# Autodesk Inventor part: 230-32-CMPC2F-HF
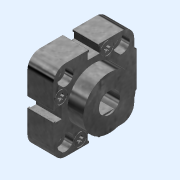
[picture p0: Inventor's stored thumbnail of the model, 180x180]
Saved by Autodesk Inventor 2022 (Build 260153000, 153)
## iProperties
Category: PARTsolutions
Company: METALWORK
Part Number: 230-32-CMPC2F-HF
Material: Generico
Catalog Web Link: www.cadenas.de
Description: CMPC2F-HF-
Vendor: METALWORK
Document SubType Name: Modeling
Designer: partserver
Manufacturer: METALWORK
Mass: 30.9361 g
Surface Area: 107.039 cm^2
Volume: 30.9361 cm^3
Density: 1 g/cm^3
Appearance: Acciaio galvanizzato
PSOL_IDENT_0: {$CADENAS_DATA\23d-libs\metalwork\actuators\comp_cyl_ser_cmpc_2_flat\parts\cmpc_2_flat_head_front.pr
PSOL_IDENT_1: j},186 {VTYP=3D},{NB=230-32-CMPC2F-HF},{LINA=230-32-CMPC2F-HF},{NN=CMPC2F-HF},{DATE=18.06.2021 08:06
PSOL_IDENT_2: :07},{GEOMDATE=01.12.2009 08:31:00},{VERSION=},{LINEID=50},{WBVAR=TYPE,VE},{WBNUMERIC=TYPE}  {NB=230
PSOL_IDENT_3: -32-CMPC2F-HF},{LINA=230-32-CMPC2F-HF},{KT=DUMMY},{IDNR=},{DI=32},{TYPE=23},{VE=0},{A=46.300},{B=32.
PSOL_IDENT_4: 25},{B2=0.000},{C=12.000},{C1=9.000},{D=47.800},{D1=9.000},{D2=7.600},{D3=7.000},{H=7.500},{H1=6.950
PSOL_IDENT_5: },{H2=5.400},{H3=14.750},{H4=2.800},{K=30.000},{L=4.500},{L1=3.700},{L2=1.200},{L3=10.000},{LD=1.700
PSOL_IDENT_6: },{O=6.000},{Q=9.728},{X=18.700},{Y=7.700},{R1=7.150},{R2=3.400},{R3=0.300},{R4=0.500},{CH=10.000}
NB: 230-32-CMPC2F-HF
NN: CMPC2F-HF
NBSYN: $TYPE.$VE.-$DI.-CMPC2F-HF
LINA: 230-32-CMPC2F-HF
CATALOG: Metalwork
DI: 32
TYPE: Centre distance to UNITOP, male rod
VE: Double-acting
A: 46.3
B: 32.25
B2: 0
C: 12
C1: 9
D: 47.8
D2: 7.6
D3: 7
H: 7.5
H1: 6.95
H2: 5.4
H3: 14.75
H4: 2.8
K: 30
L1: 3.7
L2: 1.2
L3: 10
LD: 1.7
O: 6
Q: 9.728
X: 18.7
Y: 7.7
R1: 7.15
R2: 3.4
R3: 0.3
R4: 0.5
CH: 10
SUPPLIER: METALWORK
ARTICLENO: 230-32-CMPC2F-HF
BOMINFO: 230-32-CMPC2F-HF
CREATOR: CADENAS GmbH
Title: 230-32-CMPC2F-HF
Author: Cadenas PARTsolutions
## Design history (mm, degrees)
sketch "Sketch_1"
  geometry: L1 (-23.15, 16)-(-23.15, 3.1); L2 (-22.75, 2.7)-(-22.15, 2.7); L3 (-21.95, 2.9)-(-21.95, 3.275); L4 (-21.75, 3.475)-(-18.45, 3.475); L5 (-18.25, 3.275)-(-18.25, -3.275); L6 (-18.45, -3.475)-(-21.75, -3.475); L7 (-21.95, -3.275)-(-21.95, -2.9); L8 (-22.15, -2.7)-(-22.75, -2.7); L9 (-23.15, -3.1)-(-23.15, -16); L10 (-16, -23.15)-(-3.1, -23.15); L11 (-2.7, -22.75)-(-2.7, -22.15); L12 (-2.9, -21.95)-(-3.275, -21.95); L13 (-3.475, -21.75)-(-3.475, -18.45); L14 (-3.275, -18.25)-(3.275, -18.25); L15 (3.475, -18.45)-(3.475, -21.75); L16 (3.275, -21.95)-(2.9, -21.95); L17 (2.7, -22.15)-(2.7, -22.75); L18 (3.1, -23.15)-(16, -23.15); L19 (23.15, -16)-(23.15, -10.402); L20 (23.15, -10.402)-(24.65, -10); L21 (24.65, -10)-(24.65, 10); L22 (24.65, 10)-(23.15, 10.402); L23 (23.15, 10.402)-(23.15, 16); L24 (16, 23.15)-(3.1, 23.15); L25 (2.7, 22.75)-(2.7, 22.15); L26 (2.9, 21.95)-(3.275, 21.95); L27 (3.475, 21.75)-(3.475, 18.45); L28 (3.275, 18.25)-(-3.275, 18.25); L29 (-3.475, 18.45)-(-3.475, 21.75); L30 (-3.275, 21.95)-(-2.9, 21.95); L31 (-2.7, 22.15)-(-2.7, 22.75); L32 (-3.1, 23.15)-(-16, 23.15); A1 r 7.15 centre (-16, 16) between (-16, 23.15) and (-23.15, 16); A2 r 0.4 centre (-22.75, 3.1) between (-23.15, 3.1) and (-22.75, 2.7); A3 r 0.2 centre (-22.15, 2.9) between (-22.15, 2.7) and (-21.95, 2.9); A4 r 0.2 centre (-21.75, 3.275) between (-21.75, 3.475) and (-21.95, 3.275); A5 r 0.2 centre (-18.45, 3.275) between (-18.25, 3.275) and (-18.45, 3.475); A6 r 0.2 centre (-18.45, -3.275) between (-18.45, -3.475) and (-18.25, -3.275); A7 r 0.2 centre (-21.75, -3.275) between (-21.95, -3.275) and (-21.75, -3.475); A8 r 0.2 centre (-22.15, -2.9) between (-21.95, -2.9) and (-22.15, -2.7); A9 r 0.4 centre (-22.75, -3.1) between (-22.75, -2.7) and (-23.15, -3.1); A10 r 7.15 centre (-16, -16) between (-23.15, -16) and (-16, -23.15); A11 r 0.4 centre (-3.1, -22.75) between (-3.1, -23.15) and (-2.7, -22.75); A12 r 0.2 centre (-2.9, -22.15) between (-2.7, -22.15) and (-2.9, -21.95); A13 r 0.2 centre (-3.275, -21.75) between (-3.475, -21.75) and (-3.275, -21.95); A14 r 0.2 centre (-3.275, -18.45) between (-3.275, -18.25) and (-3.475, -18.45); A15 r 0.2 centre (3.275, -18.45) between (3.475, -18.45) and (3.275, -18.25); A16 r 0.2 centre (3.275, -21.75) between (3.275, -21.95) and (3.475, -21.75); A17 r 0.2 centre (2.9, -22.15) between (2.9, -21.95) and (2.7, -22.15); A18 r 0.4 centre (3.1, -22.75) between (2.7, -22.75) and (3.1, -23.15); A19 r 7.15 centre (16, -16) between (16, -23.15) and (23.15, -16); A20 r 7.15 centre (16, 16) between (23.15, 16) and (16, 23.15); A21 r 0.4 centre (3.1, 22.75) between (3.1, 23.15) and (2.7, 22.75); A22 r 0.2 centre (2.9, 22.15) between (2.7, 22.15) and (2.9, 21.95); A23 r 0.2 centre (3.275, 21.75) between (3.475, 21.75) and (3.275, 21.95); A24 r 0.2 centre (3.275, 18.45) between (3.275, 18.25) and (3.475, 18.45); A25 r 0.2 centre (-3.275, 18.45) between (-3.475, 18.45) and (-3.275, 18.25); A26 r 0.2 centre (-3.275, 21.75) between (-3.275, 21.95) and (-3.475, 21.75); A27 r 0.2 centre (-2.9, 22.15) between (-2.9, 21.95) and (-2.7, 22.15); A28 r 0.4 centre (-3.1, 22.75) between (-2.7, 22.75) and (-3.1, 23.15)
  constraints: 64 end point, 56 point on circle, 28 centre point
extrude "Extrusion1" join sketch "Sketch_1" distance "d0" = 14.75; taper "d1" = 0 deg
sketch "Sketch2"
  geometry: 1 further point
hole "Hole1" sketch "Sketch2" at (7.5, 10) diameter "d2" = 8.566; stored, may be unused: countersink angle "d6" = 90 deg, drill point angle "d8" = 120 deg; dims "d3" = 9.728, "d4" = 4, "d5" = 2, "d7" = 14.592
sketch "Sketch_7"
  geometry: L1 (14.75, -16.125)-(0, -16.125); L2 (0, -16.125)-(0, -11.625); L3 (0, -11.625)-(4.5, -11.625); L4 (4.5, -11.625)-(4.5, -13.666); L5 (4.5, -13.666)-(14.75, -13.666); L6 (14.75, -13.666)-(14.75, -16.125); L7 (14.75, -16.125)-(0, -16.125)
  constraints: 14 end point
revolve "Revolution1" sketch "Sketch_7" stored, may be unused: angle "d9" = 360 deg
thread "Thread1" dims "d10" = 10.25, "d11" = 0
pattern_linear "Rectangular Pattern1" dims "d14" = 32.25, "d17" = 32.25
sketch "Sketch_13"
  geometry: C1 r 3.8 at (-7.7, 18.7); C2 r 3.5 at (-7.7, 18.7); 2 further points
  constraints: 2 centre point
extrude "Extrusion2" cut sketch "Sketch_13" distance "d18" = 2.8; taper "d19" = 0 deg
pattern_linear "Rectangular Pattern2" dims "d22" = 28.6, "d25" = 28.6
sketch "Sketch_19"
  geometry: L1 (-8.84, 20.095)-(-8.736, 19.706); L2 (-9.089, 19.094)-(-9.478, 18.99); L3 (-9.478, 18.41)-(-9.089, 18.306); L4 (-8.736, 17.694)-(-8.84, 17.305); L5 (-8.338, 17.016)-(-8.054, 17.3); L6 (-7.346, 17.3)-(-7.062, 17.016); L7 (-6.56, 17.305)-(-6.664, 17.694); L8 (-6.311, 18.306)-(-5.922, 18.41); L9 (-5.922, 18.99)-(-6.311, 19.094); L10 (-6.664, 19.706)-(-6.56, 20.095); L11 (-7.062, 20.384)-(-7.346, 20.1); L12 (-8.054, 20.1)-(-8.338, 20.384); A1 r 0.3 centre (-8.55, 20.172) between (-8.338, 20.384) and (-8.84, 20.095); A2 r 0.5 centre (-9.219, 19.577) between (-9.089, 19.094) and (-8.736, 19.706); A3 r 0.3 centre (-9.4, 18.7) between (-9.478, 18.99) and (-9.478, 18.41); A4 r 0.5 centre (-9.219, 17.823) between (-8.736, 17.694) and (-9.089, 18.306); A5 r 0.3 centre (-8.55, 17.228) between (-8.84, 17.305) and (-8.338, 17.016); A6 r 0.5 centre (-7.7, 16.946) between (-7.346, 17.3) and (-8.054, 17.3); A7 r 0.3 centre (-6.85, 17.228) between (-7.062, 17.016) and (-6.56, 17.305); A8 r 0.5 centre (-6.181, 17.823) between (-6.311, 18.306) and (-6.664, 17.694); A9 r 0.3 centre (-6, 18.7) between (-5.922, 18.41) and (-5.922, 18.99); A10 r 0.5 centre (-6.181, 19.577) between (-6.664, 19.706) and (-6.311, 19.094); A11 r 0.3 centre (-6.85, 20.172) between (-6.56, 20.095) and (-7.062, 20.384); A12 r 0.5 centre (-7.7, 20.454) between (-8.054, 20.1) and (-7.346, 20.1)
  constraints: 24 end point, 24 point on circle, 12 centre point
extrude "Extrusion3" cut sketch "Sketch_19" distance "d26" = 1.7; taper "d27" = 0 deg
pattern_linear "Rectangular Pattern3" dims "d30" = 28.6, "d33" = 28.6
sketch "Sketch_4"
  geometry: L1 (0, 0)-(-9, 0); L2 (-9, 0)-(-9, 15); L3 (-9, 15)-(0, 15); L4 (0, 15)-(0, 0); L5 (0, 0)-(-9, 0)
  constraints: 10 end point
revolve "Revolution2" sketch "Sketch_4" stored, may be unused: angle "d34" = 360 deg
sketch "Sketch7"
  geometry: 1 further point
hole "Hole2" sketch "Sketch7" at (0, 0) diameter "d35" = 12; stored, may be unused: countersink angle "d39" = 90 deg, drill point angle "d41" = 0 deg; dims "d36" = 6, "d37" = 4, "d38" = 2, "d40" = 23.75
sketch "Sketch_8"
  geometry: L1 (-5, 5.181)-(-5, -5.181); L2 (5, -5.181)-(5, 5.181); C1 r 8.4 at (0, 0); A1 r 7.2 centre (0, 0) between (-5, -5.181) and (5, -5.181); A2 r 7.2 centre (0, 0) between (5, 5.181) and (-5, 5.181); 1 further point
  constraints: 4 end point, 4 point on circle, 3 centre point
extrude "Extrusion4" join sketch "Sketch_8" distance "d42" = 22.85; taper "d43" = 0 deg
node "accessories_XY"
node "accessories_YZ"
node "accessories_ZX"
node "accessories_X"
node "accessories_Y"
node "accessories_Z"
node "accessories_Center"
node "head_l_XY"
node "head_l_YZ"
node "head_l_ZX"
node "head_l_X"
node "head_l_Y"
node "head_l_Z"
node "head_l_Center"
node "rod_XY"
node "rod_YZ"
node "rod_ZX"
node "rod_X"
node "rod_Y"
node "rod_Z"
node "rod_Center"
body "Solid1"
other parameters: "d44" = 0, "d45" = 0, "d46" = 0
